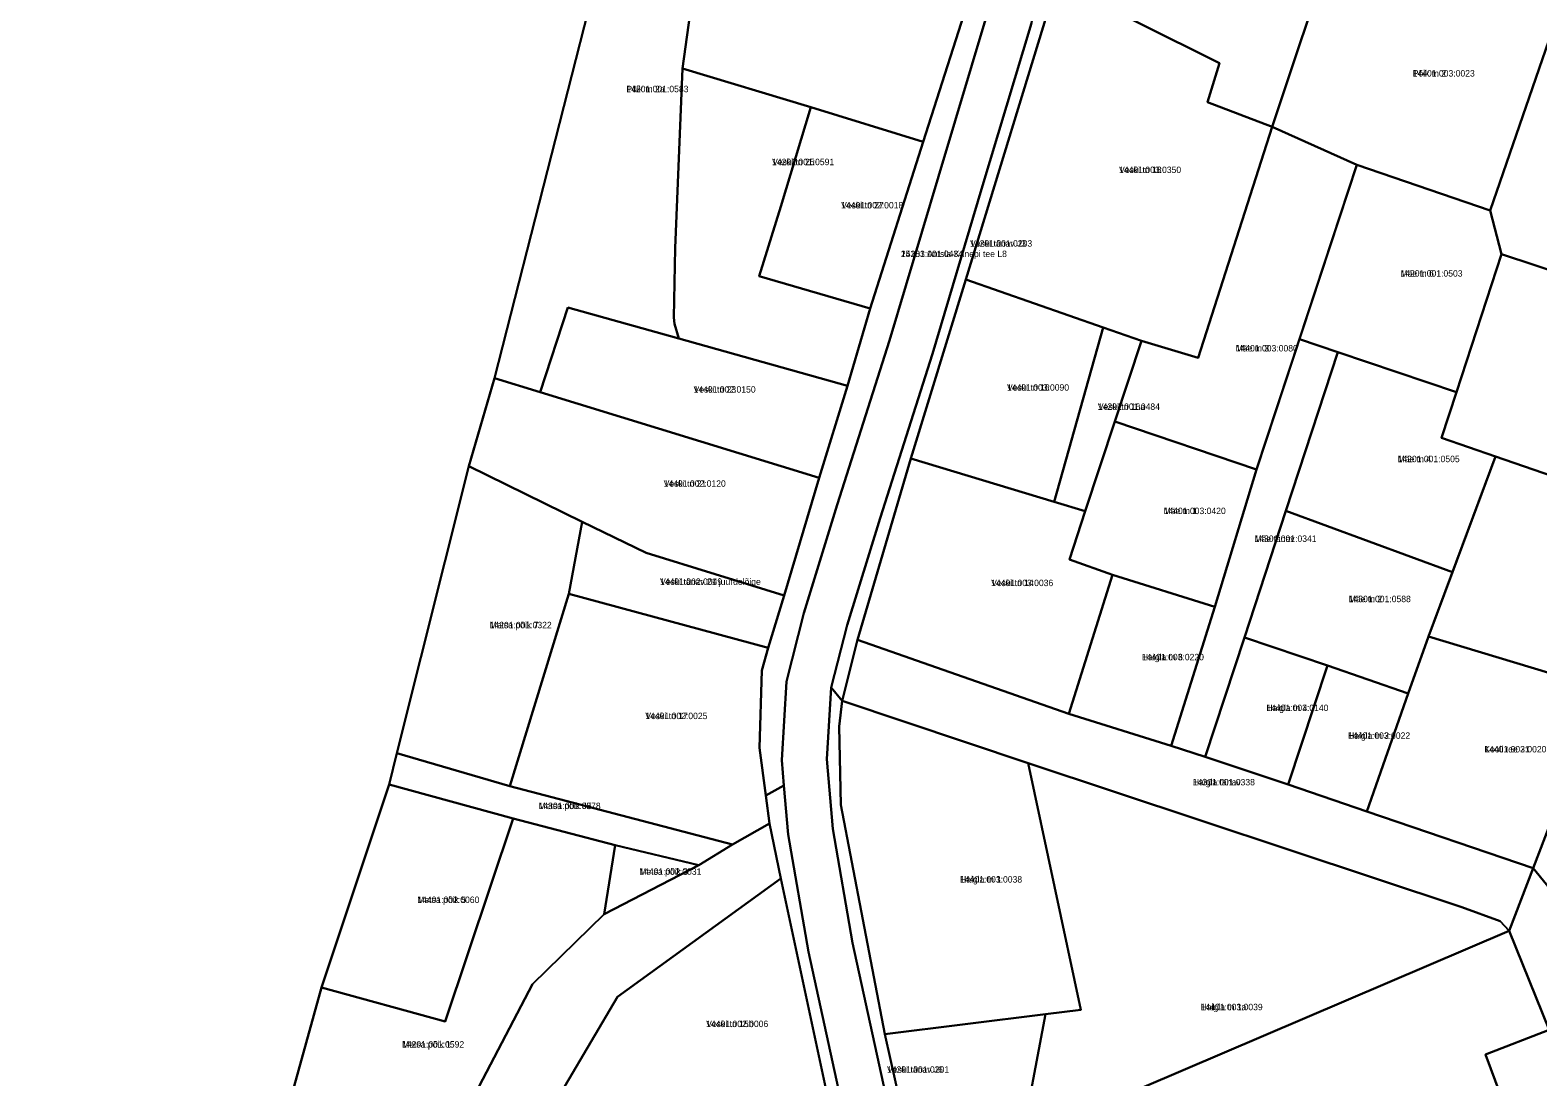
# Model space of a CAD drawing. Extents: x 640657 to 665127, y 6395726 to 6426831.
# Drawn here: x 649927.4 to 650279.6, y 6412875.2 to 6413119.6 of the extents above; entities that cross this region are included whole.
import ezdxf

# ---------------------------------------------------------------- set-up
doc = ezdxf.new("R2010")
doc.units = 0
for name, color, linetype in [('L_AADRESS', 7, 'Continuous'), ('PIIR', 7, 'Continuous'), ('TUNNUS', 7, 'Continuous')]:
    doc.layers.add(name, color=color, linetype=linetype)

msp = doc.modelspace()

# ---------------------------------------------------------------- linework, layer by layer
at = {"layer": 'PIIR'}
for points in [[(650075.82, 6413194.87), (650035.9, 6413038.33), (650029.91, 6413017.75), (650013.12, 6412950.76), (650011.32, 6412943.44), (649995.48, 6412896.01), (649979.35, 6412837.85), (649912.58, 6412835.05), (649873.8, 6412751.6), (649783.99, 6412761.55), (649725.8, 6412733.89), (649702.61, 6412730.39), (649660.39, 6412727.03), (649637.16, 6412726.43), (649580.19, 6412722.52), (649451.05, 6412725.29)], [(650118.56, 6412861.55), (650109.28, 6412904.36), (650104.49, 6412931.77), (650103.52, 6412943.21), (650103.02, 6412949.07), (650104.1, 6412967.48), (650108.17, 6412983.47), (650115.96, 6413008.76), (650128.17, 6413047.11), (650139.59, 6413085.42), (650151.32, 6413124.41)], [(650161.33, 6413121.23), (650149.65, 6413082.41), (650138.2, 6413044.01), (650125.98, 6413005.63), (650118.28, 6412980.62), (650114.58, 6412966.11), (650113.52, 6412949.33), (650114.91, 6412933.04), (650119.56, 6412906.45), (650128.85, 6412863.68)], [(650282.26, 6412886.17), (650272.9, 6412909.24), (650278.55, 6412923.91), (650292.03, 6412907.35)]]:
    msp.add_lwpolyline(points, dxfattribs=at)
for points in [[(650053.05, 6413054.85), (650046.56, 6413035.05), (650035.9, 6413038.33), (650075.82, 6413194.87), (650097.53, 6413189.24), (650085.35, 6413150.63), (650079.83, 6413110.66), (650078.11, 6413068.7), (650077.81, 6413052.49), (650077.98, 6413050.97), (650078.94, 6413047.59)], [(650099.26, 6412940.85), (650097.8, 6412951.97), (650098.39, 6412970.02), (650099.86, 6412975.31), (650103.54, 6412987.57), (650111.77, 6413015.03), (650118.39, 6413036.54), (650123.68, 6413054.55), (650136.05, 6413093.47), (650148.08, 6413131.26), (650159.32, 6413167.5), (650161.47, 6413166.96), (650163.89, 6413166.35), (650151.32, 6413124.41), (650139.59, 6413085.42), (650128.17, 6413047.11), (650115.96, 6413008.76), (650108.17, 6412983.47), (650104.1, 6412967.48), (650103.02, 6412949.07), (650103.52, 6412943.21)], [(650114.58, 6412966.11), (650118.28, 6412980.62), (650125.98, 6413005.63), (650138.2, 6413044.01), (650149.65, 6413082.41), (650161.33, 6413121.23), (650175.9, 6413169.89), (650177.31, 6413169.39), (650179.43, 6413168.68), (650177.25, 6413162.18), (650167.28, 6413130.84), (650146.04, 6413061.36), (650133.13, 6413019.53), (650120.7, 6412977.2), (650117.14, 6412962.99)], [(650177.25, 6413162.18), (650231.92, 6413140.01), (650217.56, 6413097.01), (650202.49, 6413102.73), (650205.23, 6413111.89), (650167.28, 6413130.84)], [(650148.08, 6413131.26), (650136.05, 6413093.47), (650109.82, 6413101.56), (650079.83, 6413110.66), (650085.35, 6413150.63)], [(650217.56, 6413097.01), (650231.92, 6413140.01), (650283.94, 6413122.19), (650282.18, 6413117.13), (650268.45, 6413077.48), (650237.31, 6413088.1)], [(650167.28, 6413130.84), (650205.23, 6413111.89), (650202.49, 6413102.73), (650217.56, 6413097.01), (650200.28, 6413043.05), (650187.07, 6413047), (650178.1, 6413050.15), (650146.04, 6413061.36)], [(650282.18, 6413117.13), (650312.64, 6413105.72), (650306.45, 6413086.49), (650335.26, 6413075.19), (650325.62, 6413049.27), (650271.11, 6413067.27), (650268.45, 6413077.48)], [(650097.71, 6413062.1), (650123.68, 6413054.55), (650118.39, 6413036.54), (650078.94, 6413047.59), (650077.98, 6413050.97), (650077.81, 6413052.49), (650078.11, 6413068.7), (650079.83, 6413110.66), (650109.82, 6413101.56), (650102.82, 6413078.4)], [(650136.05, 6413093.47), (650123.68, 6413054.55), (650097.71, 6413062.1), (650102.82, 6413078.4), (650109.82, 6413101.56)], [(650180.8, 6413028.22), (650187.07, 6413047), (650200.28, 6413043.05), (650217.56, 6413097.01), (650237.31, 6413088.1), (650213.93, 6413017)], [(650342.53, 6413094.26), (650360.4, 6413086.12), (650343.5, 6413041.6), (650328.69, 6413002.34), (650311.89, 6412962.22), (650309.49, 6412955.73), (650298.99, 6412925.64), (650292.03, 6412907.35), (650278.55, 6412923.91), (650294.57, 6412965.73), (650309.67, 6413006.23), (650325.62, 6413049.27), (650335.26, 6413075.19)], [(650271.11, 6413067.27), (650260.59, 6413035.01), (650232.9, 6413044.4), (650223.95, 6413047.41), (650237.31, 6413088.1), (650268.45, 6413077.48)], [(650271.11, 6413067.27), (650325.62, 6413049.27), (650309.67, 6413006.23), (650269.73, 6413020.05), (650257.13, 6413024.41), (650260.59, 6413035.01)], [(650146.04, 6413061.36), (650178.1, 6413050.15), (650166.6, 6413009.45), (650133.13, 6413019.53)], [(650053.05, 6413054.85), (650078.94, 6413047.59), (650118.39, 6413036.54), (650111.77, 6413015.03), (650046.56, 6413035.05)], [(650180.8, 6413028.22), (650173.91, 6413007.23), (650166.6, 6413009.45), (650178.1, 6413050.15), (650187.07, 6413047)], [(650193.96, 6412952.47), (650204.15, 6412984.91), (650213.93, 6413017), (650223.95, 6413047.41), (650232.9, 6413044.4), (650220.78, 6413007.31), (650211.12, 6412977.73), (650201.9, 6412949.92)], [(650269.73, 6413020.05), (650259.67, 6412992.99), (650220.78, 6413007.31), (650232.9, 6413044.4), (650260.59, 6413035.01), (650257.13, 6413024.41)], [(650111.77, 6413015.03), (650103.54, 6412987.57), (650071.3, 6412997.49), (650056.42, 6413004.78), (650029.91, 6413017.75), (650035.9, 6413038.33), (650046.56, 6413035.05)], [(650213.93, 6413017), (650204.15, 6412984.91), (650180.29, 6412992.4), (650170.22, 6412995.96), (650173.91, 6413007.23), (650180.8, 6413028.22)], [(650133.13, 6413019.53), (650166.6, 6413009.45), (650173.91, 6413007.23), (650170.22, 6412995.96), (650180.29, 6412992.4), (650170.1, 6412959.96), (650120.7, 6412977.2)], [(650254.08, 6412977.96), (650269.73, 6413020.05), (650309.67, 6413006.23), (650294.57, 6412965.73)], [(650013.12, 6412950.76), (650029.91, 6413017.75), (650056.42, 6413004.78), (650053.28, 6412987.95), (650039.46, 6412943.07)], [(650056.42, 6413004.78), (650071.3, 6412997.49), (650103.54, 6412987.57), (650099.86, 6412975.31), (650053.28, 6412987.95)], [(650211.12, 6412977.73), (650220.78, 6413007.31), (650259.67, 6412992.99), (650254.08, 6412977.96), (650249.29, 6412964.7), (650230.49, 6412971.19)], [(650193.96, 6412952.47), (650170.1, 6412959.96), (650180.29, 6412992.4), (650204.15, 6412984.91)], [(650099.86, 6412975.31), (650098.39, 6412970.02), (650097.8, 6412951.97), (650099.26, 6412940.85), (650100.12, 6412934.32), (650091.47, 6412929.42), (650039.46, 6412943.07), (650053.28, 6412987.95)], [(650120.7, 6412977.2), (650170.1, 6412959.96), (650193.96, 6412952.47), (650201.9, 6412949.92), (650221.29, 6412943.41), (650239.67, 6412937.15), (650278.55, 6412923.91), (650272.9, 6412909.24), (650270.8, 6412911.5), (650261.9, 6412914.8), (650160.6, 6412948.4), (650117.14, 6412962.99)], [(650230.49, 6412971.19), (650221.29, 6412943.41), (650201.9, 6412949.92), (650211.12, 6412977.73)], [(650249.29, 6412964.7), (650254.08, 6412977.96), (650294.57, 6412965.73), (650278.55, 6412923.91), (650239.67, 6412937.15)], [(650239.67, 6412937.15), (650221.29, 6412943.41), (650230.49, 6412971.19), (650249.29, 6412964.7)], [(650138.9, 6412820.05), (650134.56, 6412839.42), (650128.85, 6412863.68), (650119.56, 6412906.45), (650114.91, 6412933.04), (650113.52, 6412949.33), (650114.58, 6412966.11), (650117.14, 6412962.99), (650116.4, 6412957), (650116.8, 6412938.7), (650127.07, 6412885.11), (650133.7, 6412855.52), (650139.23, 6412833.01), (650141.67, 6412823.06)], [(650117.14, 6412962.99), (650160.6, 6412948.4), (650172.9, 6412890.8), (650164.6, 6412889.76), (650127.07, 6412885.11), (650116.8, 6412938.7), (650116.4, 6412957)], [(650011.32, 6412943.44), (650013.12, 6412950.76), (650039.46, 6412943.07), (650091.47, 6412929.42), (650083.62, 6412924.59), (650064.09, 6412929.28), (650040.26, 6412935.52)], [(650160.6, 6412948.4), (650261.9, 6412914.8), (650270.8, 6412911.5), (650272.9, 6412909.24), (650187.12, 6412872.57), (650197.94, 6412840.41), (650139.23, 6412833.01), (650133.7, 6412855.52), (650158.62, 6412858.03), (650164.6, 6412889.76), (650172.9, 6412890.8)], [(649995.48, 6412896.01), (650011.32, 6412943.44), (650040.26, 6412935.52), (650024.41, 6412888.09)], [(650100.12, 6412934.32), (650099.26, 6412940.85), (650103.52, 6412943.21), (650104.49, 6412931.77), (650109.28, 6412904.36), (650118.56, 6412861.55), (650124.34, 6412836.99), (650128.41, 6412818.65), (650129.76, 6412813.51), (650139.04, 6412776.8), (650150.14, 6412738.26), (650152.3, 6412731.02), (650150.59, 6412731), (650149.05, 6412736.51), (650135.86, 6412777.87), (650131.21, 6412798), (650125.27, 6412822.22), (650123.55, 6412832.47), (650114.73, 6412869.35), (650114.02, 6412869.15), (650102.81, 6412921.46)], [(649957.5, 6412752.07), (650009.04, 6412828.45), (650044.8, 6412896.8), (650061.49, 6412913.16), (650083.62, 6412924.59), (650091.47, 6412929.42), (650100.12, 6412934.32), (650102.81, 6412921.46), (650064.61, 6412893.83), (650040.04, 6412852.08), (650018.22, 6412814.34), (649983.85, 6412765.83), (649975.94, 6412754.7)], [(649995.47, 6412895.99), (650024.41, 6412888.09), (650040.26, 6412935.52), (650064.09, 6412929.28), (650061.49, 6412913.16), (650044.8, 6412896.8), (650009.04, 6412828.45), (649993.91, 6412836.34), (649979.35, 6412837.85)], [(650064.09, 6412929.28), (650083.62, 6412924.59), (650061.49, 6412913.16)], [(650102.81, 6412921.46), (650114.02, 6412869.15), (650072.73, 6412859.57), (650040.04, 6412852.08), (650064.61, 6412893.83)], [(650210.67, 6412800.52), (650208.07, 6412813.16), (650204.13, 6412822.35), (650201.08, 6412831.03), (650197.94, 6412840.41), (650187.12, 6412872.57), (650272.9, 6412909.24), (650282.26, 6412886.17), (650267.38, 6412880.34), (650282.69, 6412839.36), (650264.5, 6412831.05), (650245.1, 6412820.91), (650237.85, 6412816.79), (650224.05, 6412807.61)], [(650127.07, 6412885.11), (650164.6, 6412889.76), (650158.62, 6412858.03), (650133.7, 6412855.52)], [(650267.38, 6412880.34), (650282.26, 6412886.17), (650285.9, 6412881.2), (650299.3, 6412846.7), (650282.69, 6412839.36)]]:
    msp.add_lwpolyline(points, close=True, dxfattribs=at)

# ---------------------------------------------------------------- texts
at = {"layer": 'L_AADRESS'}
for s, p in [('Põik tn 2', (650250.38, 6413108.75)), ('Põik tn 2a', (650066.71, 6413105.09)), ('Veski tn 25', (650100.75, 6413088.05)), ('Veski tn 18', (650181.8, 6413086.22)), ('Veski tn 27', (650116.88, 6413077.95)), ('25183 Antsla-Kanepi tee L8', (650130.84, 6413066.59)), ('Veski tänav J3', (650147, 6413069.03)), ('Mäe tn 6', (650247.53, 6413062.03)), ('Mäe tn 3', (650209.05, 6413044.55)), ('Veski tn 23', (650082.41, 6413034.94)), ('Veski tn 16', (650155.62, 6413035.39)), ('Veski tn 16a', (650176.84, 6413030.91)), ('Mäe tn 4', (650246.86, 6413018.69)), ('Veski tn 21', (650075.43, 6413012.95)), ('Mäe tn 1', (650192.22, 6413006.57)), ('Mäe tänav', (650213.43, 6413000.08)), ('Veski tänav 21 juurdelõige', (650074.58, 6412990.04)), ('Veski tn 14', (650151.92, 6412989.75)), ('Mäe tn 2', (650235.45, 6412986)), ('Metsa põik 7', (650034.77, 6412979.91)), ('Haigla tn 6', (650187.12, 6412972.43)), ('Veski tn 17', (650071.14, 6412958.69)), ('Haigla tn 4', (650216.2, 6412960.57)), ('Haigla tn 2', (650235.29, 6412954.09)), ('Kooli tee 21', (650267.12, 6412950.91)), ('Haigla tänav', (650199.03, 6412943.22)), ('Metsa põik J5', (650046.2, 6412937.68)), ('Metsa põik 3', (650069.73, 6412922.34)), ('Haigla tn 1', (650144.65, 6412920.52)), ('Metsa põik 5', (650017.87, 6412915.76)), ('Haigla tn 1a', (650200.84, 6412890.71)), ('Veski tn 15b', (650085.35, 6412886.77)), ('Metsa põik 1', (650014.32, 6412881.99)), ('Veski tänav J6', (650127.6, 6412876.11))]:
    msp.add_text(s, height=1.5, dxfattribs=at).set_placement(p)
at = {"layer": 'TUNNUS'}
for s, p in [('14401:003:0023', (650250.38, 6413108.75)), ('14201:001:0583', (650066.71, 6413105.09)), ('14201:001:0591', (650100.75, 6413088.05)), ('14401:003:0350', (650181.8, 6413086.22)), ('14401:002:0018', (650116.88, 6413077.95)), ('14201:001:0203', (650147, 6413069.03)), ('14201:001:0434', (650130.84, 6413066.59)), ('14201:001:0503', (650247.53, 6413062.03)), ('14401:003:0080', (650209.05, 6413044.55)), ('14401:002:0150', (650082.41, 6413034.94)), ('14401:003:0090', (650155.62, 6413035.39)), ('14201:001:0484', (650176.84, 6413030.91)), ('14201:001:0505', (650246.86, 6413018.69)), ('14401:002:0120', (650075.43, 6413012.95)), ('14401:003:0420', (650192.22, 6413006.57)), ('14301:001:0341', (650213.43, 6413000.08)), ('14401:002:0049', (650074.58, 6412990.04)), ('14401:003:0036', (650151.92, 6412989.75)), ('14301:001:0588', (650235.45, 6412986)), ('14201:001:0322', (650034.77, 6412979.91)), ('14401:003:0220', (650187.12, 6412972.43)), ('14401:002:0025', (650071.14, 6412958.69)), ('14401:003:0140', (650216.2, 6412960.57)), ('14401:003:0022', (650235.29, 6412954.09)), ('14401:003:0020', (650267.12, 6412950.91)), ('14301:001:0338', (650199.03, 6412943.22)), ('14301:001:0378', (650046.2, 6412937.68)), ('14401:002:0031', (650069.73, 6412922.34)), ('14401:003:0038', (650144.65, 6412920.52)), ('14401:002:0060', (650017.87, 6412915.76)), ('14401:003:0039', (650200.84, 6412890.71)), ('14401:002:0006', (650085.35, 6412886.77)), ('14201:001:0592', (650014.32, 6412881.99)), ('14201:001:0201', (650127.6, 6412876.11))]:
    msp.add_text(s, height=1.5, dxfattribs=at).set_placement(p)

doc.saveas('drawing.dxf')
